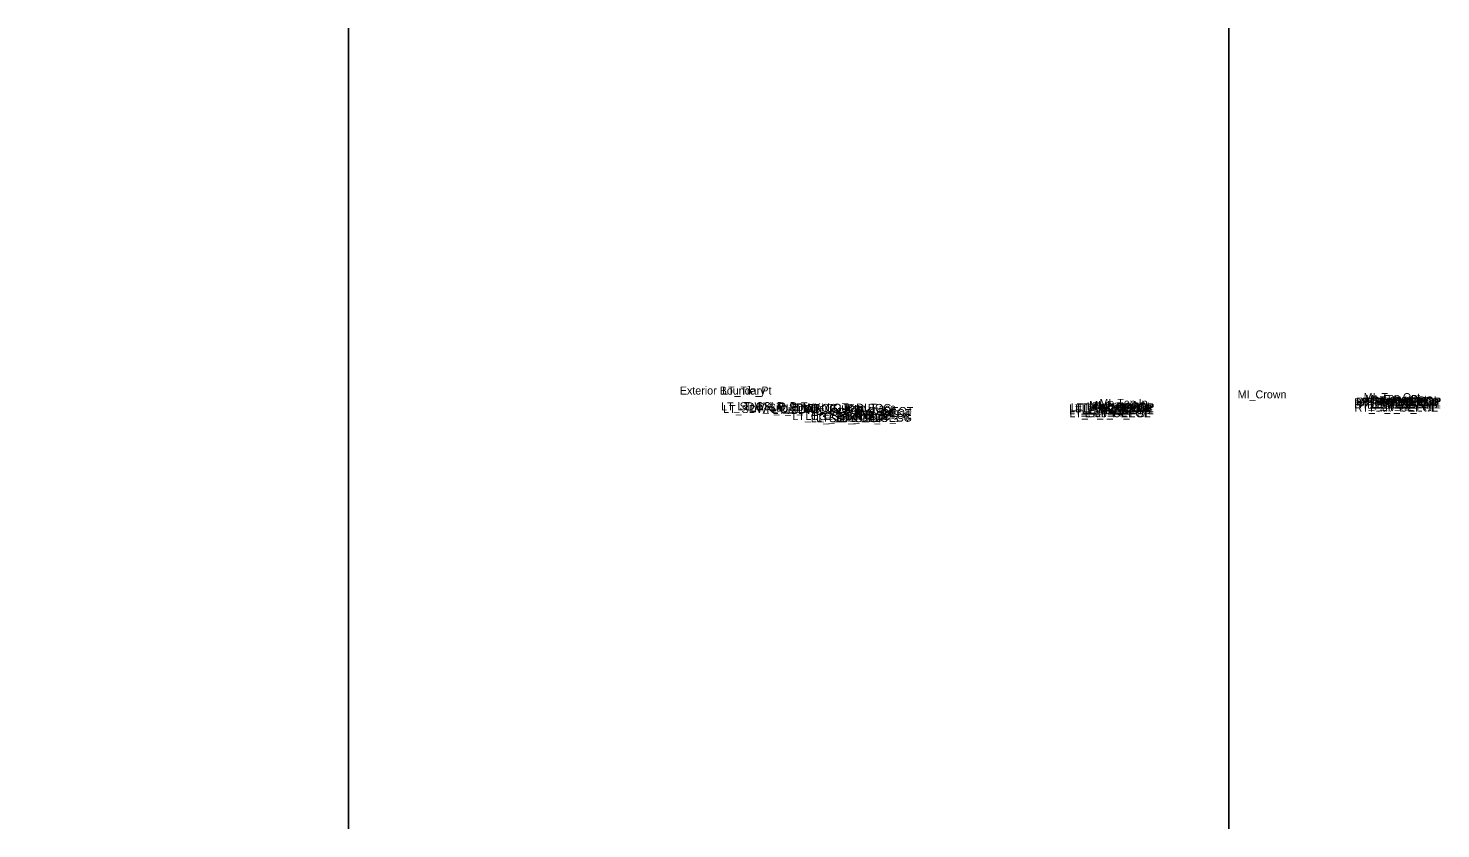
# Model space of a CAD drawing. Extents: x 0 to 6300, y -50 to 9550.
# Drawn here: x 3000 to 3176.5, y 4950 to 5050 of the extents above; entities that cross this region are included whole.
import ezdxf

# ---------------------------------------------------------------- set-up
doc = ezdxf.new("R2010")
doc.units = 0
for name, color, linetype in [('Default', 7, 'Continuous'), ('Prop XS Exc Vertical Line 1', 7, 'Continuous'), ('Prop XS Exc Vertical Line 2', 7, 'Continuous')]:
    doc.layers.add(name, color=color, linetype=linetype)

msp = doc.modelspace()

# ---------------------------------------------------------------- linework, layer by layer
at = {"layer": 'Prop XS Exc Vertical Line 1'}
msp.add_line((3040, 5050), (3040, 4950), dxfattribs=at)
at = {"layer": 'Prop XS Exc Vertical Line 2'}
msp.add_line((3150, 5050), (3150, 4950), dxfattribs=at)

# ---------------------------------------------------------------- texts
at = {"layer": 'Default'}
for s, height, p in [('Exterior Boundary', 1, (3081.41, 5004.24)), ('LT_Tie_Pt', 1, (3086.69, 5004.24)), ('LT_SDWK_Out_Top', 1, (3086.58, 5002.26)), ('LT_CSLP_Pnt', 1, (3088.6, 5002.29)), ('LT_PV1_PGL', 1, (3132.25, 5002.28)), ('MI_Face In', 1, (3132.55, 5002.45)), ('MI_Bot In', 1, (3133.72, 5002.28)), ('MI_Top In', 1, (3133.84, 5002.7)), ('MI_Crown', 1, (3151.11, 5003.76)), ('RT_PV2_OEEOP', 1, (3165.67, 5002.75)), ('RT_PV3_OEEOP', 1, (3165.67, 5002.5)), ('RT_PV1_OEEOP', 1, (3165.91, 5002.87)), ('RT_PV2_IEEOP', 1, (3166.43, 5002.75)), ('RT_PV1_IEEOP', 1, (3166.67, 5002.87)), ('MI_Top Out', 1, (3166.85, 5003.42)), ('MI_Face Out', 1, (3167.06, 5003.17)), ('RT_PV2_PGL1', 1, (3167.27, 5002.75)), ('RT_PV3_PGL1', 1, (3167.27, 5002.5)), ('RT_PV2_PGL', 1, (3167.65, 5002.75)), ('RT_PV1_PGL', 1, (3167.88, 5003)), ('MI_Bot Out', 1, (3168.25, 5003)), ('LT_SDWK_Out_Bot', 1, (3086.83, 5001.93)), ('LT_Sub_Trench_Out_DLT', 1, (3090.22, 5002.11)), ('LT_SDWK_In_Top', 1, (3092.74, 5002.16)), ('LT_SDWK_In_Bot', 1, (3092.99, 5001.83)), ('LT_CG1_Shelf_Out', 1, (3095.48, 5001.05)), ('LT_CG_Top_BOC', 1, (3096.81, 5002.07)), ('LT_CG_Bot_BOC', 1, (3097.09, 5001.06)), ('LT_CG_Top_Face', 1, (3097.34, 5002.07)), ('LT_Sub_OEOP', 1, (3097.77, 5000.79)), ('LT_CG_Top_Gut', 1, (3097.87, 5001.57)), ('LT_Sub_OEOT_CG', 1, (3098.44, 5000.86)), ('LT_PV2_OEOT', 1, (3100.99, 5001.44)), ('LT_PV3_OEOT', 1, (3100.99, 5001.19)), ('LT_Sub_OEOT', 1, (3101.04, 5000.81)), ('LT_PV1_OEOT', 1, (3101.23, 5001.69)), ('LT_CG_Bot_IE', 1, (3101.34, 5001.11)), ('LT_PV2_OEEOP', 1, (3130.04, 5002.03)), ('LT_PV3_OEEOP', 1, (3130.04, 5001.78)), ('LT_Sub_OEEOP', 1, (3130.08, 5001.41)), ('LT_PV1_OEEOP', 1, (3130.27, 5002.16)), ('LT_PV2_IEEOP', 1, (3130.8, 5002.03)), ('LT_PV1_IEEOP', 1, (3131.04, 5002.16)), ('LT_PV2_PGL1', 1, (3131.63, 5002.03)), ('LT_PV3_PGL1', 1, (3131.63, 5001.78)), ('LT_PV2_PGL', 1, (3132.01, 5002.03)), ('LT_PV4_PGL', 1, (3132.01, 5001.41)), ('RT_Sub_OEEOP', 1, (3165.71, 5002.12)), ('RT_PV4_PGL', 1, (3167.65, 5002.12)), ('-', 0.0001, (3000, 5000))]:
    msp.add_text(s, height=height, dxfattribs=at).set_placement(p)

doc.saveas('drawing.dxf')
